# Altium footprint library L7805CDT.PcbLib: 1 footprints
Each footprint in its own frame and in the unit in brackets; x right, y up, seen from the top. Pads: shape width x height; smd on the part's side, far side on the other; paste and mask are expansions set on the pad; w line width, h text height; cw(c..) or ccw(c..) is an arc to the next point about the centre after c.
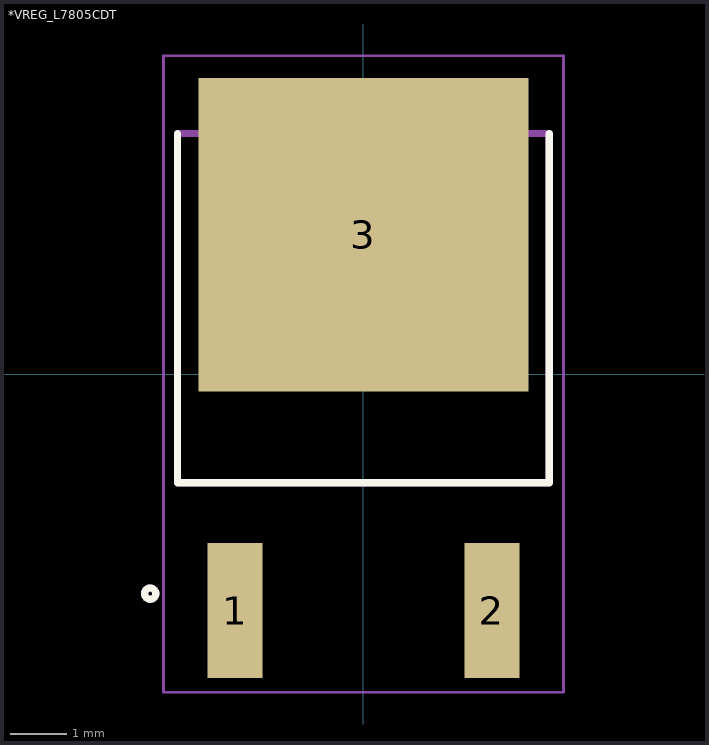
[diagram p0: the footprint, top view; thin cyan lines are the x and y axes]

## *VREG_L7805CDT [mm]
pads (3):
  rect 0.98x2.4 smd: 1(-2.28,-4.2) 2(2.28,-4.2)
  rect 5.86x5.57 smd: 3(0,2.47)
Top Overlay:
  circle w0.127: c-3.786,-3.9 r0.1
  lines w0.127: -3.3,4.27 -3.3,-1.93 3.3,-1.93 3.3,4.27
Mechanical 4:
  circle w0.127: c-3.786,-3.9 r0.1
  circle w0.127: c-3.786,-3.9 r0.1
  lines w0.127: -3.3,-1.93 -3.3,4.27 ; -3.3,-1.93 3.3,-1.93 ; -3.3,-1.93 -3.3,4.27 ; -3.3,-1.93 3.3,-1.93 ; -3.3,4.27 3.3,4.27 ; -3.3,4.27 3.3,4.27 ; 3.3,-1.93 3.3,4.27 ; 3.3,-1.93 3.3,4.27
Mechanical 16:
  lines w0.05: -3.55,-5.65 3.55,-5.65 3.55,5.65 -3.55,5.65 -3.55,-5.65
